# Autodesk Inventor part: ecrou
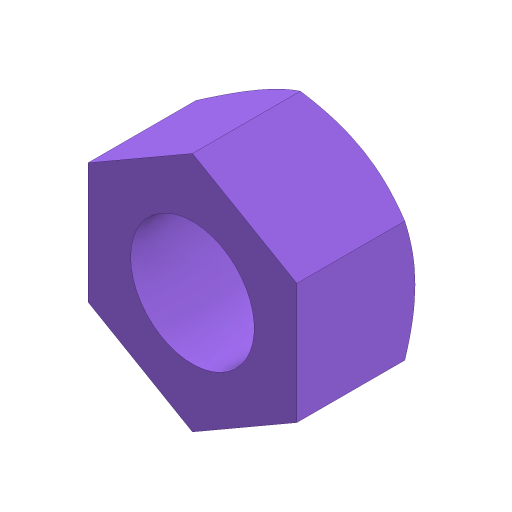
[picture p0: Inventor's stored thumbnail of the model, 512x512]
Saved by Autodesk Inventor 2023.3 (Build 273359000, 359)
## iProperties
Created: 2024-11
Part Number: ecrou
Material: Générique
Description: STEP AP203
Document SubType Name: Modeling
Designer: Thier
Density: 1 g/cm^3
Appearance: Violet
Sending System: SolidWorks 2017
Preprocessor: SwSTEP 2.0
Title: ecrou.STEP
Revision Number: ANY
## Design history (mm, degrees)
feature "Enlever de la matière-Balayage1"
node "Solide1"
